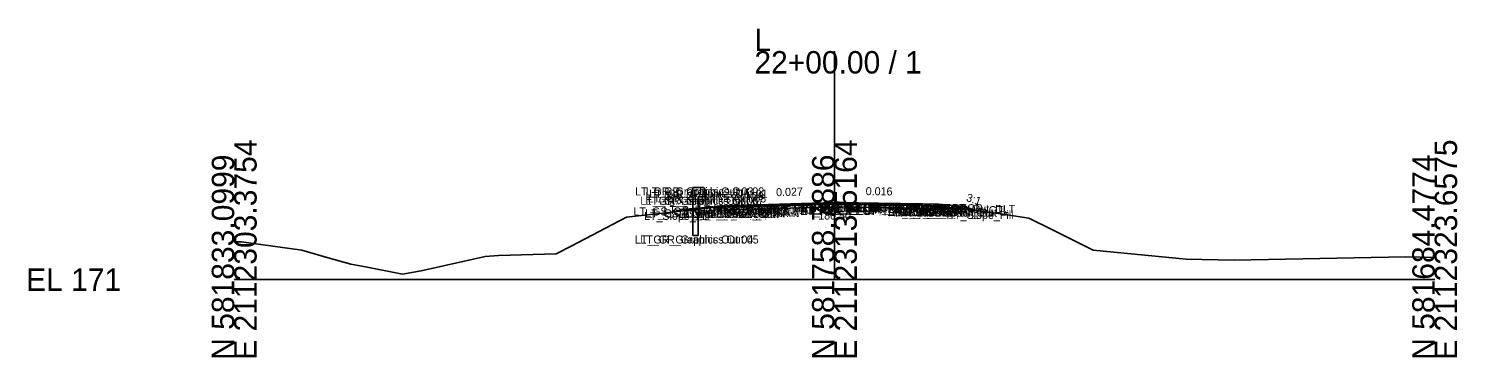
# Model space of a CAD drawing. Extents: x -486 to 1153, y -333 to 9539.
# Drawn here: x 974.3 to 1152.8, y 2990.3 to 3031.3 of the extents above; entities that cross this region are included whole.
import ezdxf

# ---------------------------------------------------------------- set-up
doc = ezdxf.new("R2010")
doc.units = 0
for name, color, linetype in [('Default', 7, 'Continuous'), ('Exist CMT Pavement', 7, 'Continuous'), ('Exist Cross Section Cell', 7, 'Continuous'), ('Exist XS Ground Line', 7, 'Continuous'), ('Prop CMT Guardrail Graphics', 7, 'Continuous'), ('Prop CMT Pvmt Course 1', 7, 'Continuous'), ('Prop CMT Pvmt Course 1 Wedge', 7, 'Continuous'), ('Prop CMT Pvmt Course 2', 7, 'Continuous'), ('Prop CMT Pvmt Course 2 Wedge', 7, 'Continuous'), ('Prop CMT Pvmt Course 3', 7, 'Continuous'), ('Prop CMT Pvmt Course 3 Wedge', 7, 'Continuous'), ('Prop CMT Pvmt Surface', 7, 'Continuous'), ('Prop CMT Pvmt Surface Shoulder', 7, 'Continuous'), ('Prop CMT Pvmt Wedge Surface 1', 7, 'Continuous'), ('Prop CMT Pvmt Wedge Surface 2', 7, 'Continuous'), ('Prop CMT Pvmt Wedge Surface 3', 7, 'Continuous'), ('Prop CMT Shld Paved Course 1', 7, 'Continuous'), ('Prop CMT Shld Paved Course 2', 7, 'Continuous'), ('Prop CMT Shld Paved Course 3', 7, 'Continuous'), ('Prop CMT Slope Grass', 7, 'Continuous'), ('Prop CMT Subgrade Earthwork', 7, 'Continuous'), ('Prop XS Earthwork Shape', 7, 'Continuous'), ('Prop XS SE Text', 7, 'Continuous'), ('Prop XS Side Slope Text', 7, 'Continuous'), ('Scratch_Level_0', 7, 'Continuous'), ('Scratch_Level_1', 7, 'Continuous')]:
    doc.layers.add(name, color=color, linetype=linetype)

msp = doc.modelspace()

# ---------------------------------------------------------------- linework, layer by layer
at = {"layer": 'Exist CMT Pavement'}
for points in [[(1065.45, 3009.24), (1075, 3009.5)], [(1075, 3009.5), (1084.6, 3009.35)]]:
    msp.add_lwpolyline(points, dxfattribs=at)
at = {"layer": 'Exist Cross Section Cell'}
for p, q in [((1075, 3000), (1075, 3028.51)), ((1000, 3000), (1075, 3000)), ((1075, 3000), (1150, 3000))]:
    msp.add_line(p, q, dxfattribs=at)
at = {"layer": 'Exist XS Ground Line'}
for p, q in [((1049.03, 3007.8), (1054.27, 3008.38)), ((1054.27, 3008.38), (1059.55, 3008.97)), ((1059.55, 3008.97), (1065.45, 3009.24)), ((1065.45, 3009.24), (1068.43, 3009.32)), ((1068.43, 3009.32), (1074.94, 3009.5)), ((1074.94, 3009.5), (1077.98, 3009.47)), ((1077.98, 3009.47), (1084.61, 3009.35)), ((1084.61, 3009.35), (1090.42, 3008.86)), ((1090.42, 3008.86), (1094.92, 3008.34)), ((1094.92, 3008.34), (1099.29, 3007.67)), ((1042.12, 3004.19), (1049.03, 3007.8)), ((1099.29, 3007.67), (1102.18, 3006.24)), ((1000, 3004.73), (1000.92, 3004.73)), ((1000.92, 3004.73), (1008.46, 3003.69)), ((1102.18, 3006.24), (1107.34, 3003.66)), ((1008.46, 3003.69), (1011.46, 3002.82)), ((1031.34, 3002.89), (1033.01, 3003)), ((1033.01, 3003), (1040.22, 3003.22)), ((1040.22, 3003.22), (1042.12, 3004.19)), ((1107.34, 3003.66), (1118.95, 3002.56)), ((1011.46, 3002.82), (1014.58, 3001.95)), ((1014.58, 3001.95), (1016.39, 3001.58)), ((1016.39, 3001.58), (1021.02, 3000.69)), ((1023.38, 3001.1), (1031.34, 3002.89)), ((1118.95, 3002.56), (1124.96, 3002.44)), ((1124.96, 3002.44), (1146.35, 3002.85)), ((1146.35, 3002.85), (1150, 3002.76)), ((1021.02, 3000.69), (1023.38, 3001.1))]:
    msp.add_line(p, q, dxfattribs=at)
at = {"layer": 'Prop CMT Guardrail Graphics'}
for points in [[(1057.3, 3005.51), (1057.3, 3011.51)], [(1057.3, 3011.51), (1058.63, 3011.51), (1058.9, 3011.22)], [(1058.9, 3010.63), (1058.63, 3010.34), (1057.96, 3010.34)], [(1057.96, 3010.34), (1057.96, 3005.51)], [(1058.9, 3011.22), (1058.63, 3010.93)], [(1058.63, 3010.93), (1058.9, 3010.63)], [(1057.96, 3005.51), (1057.3, 3005.51)]]:
    msp.add_lwpolyline(points, dxfattribs=at)
at = {"layer": 'Prop CMT Pvmt Course 1'}
for points in [[(1075, 3009.61), (1064, 3009.31)], [(1064, 3009.31), (1064, 3009.1)], [(1064, 3009.1), (1065.45, 3009.14)], [(1065.45, 3009.23), (1075, 3009.49)], [(1065.45, 3009.14), (1065.45, 3009.23)], [(1075, 3009.4), (1075, 3009.61)], [(1075, 3009.61), (1086, 3009.44)], [(1075, 3009.4), (1075, 3009.61)], [(1075, 3009.49), (1075, 3009.4), (1075, 3009.4)], [(1084.61, 3009.33), (1075, 3009.49)], [(1075, 3009.49), (1075, 3009.4), (1075, 3009.4)], [(1084.61, 3009.25), (1084.61, 3009.33)], [(1086, 3009.23), (1084.61, 3009.25)], [(1086, 3009.44), (1086, 3009.23)]]:
    msp.add_lwpolyline(points, dxfattribs=at)
at = {"layer": 'Prop CMT Pvmt Course 1 Wedge'}
for points in [[(1075, 3009.49), (1065.45, 3009.23)], [(1075, 3009.49), (1084.61, 3009.33)]]:
    msp.add_lwpolyline(points, dxfattribs=at)
at = {"layer": 'Prop CMT Pvmt Course 2'}
for points in [[(1065.45, 3009.14), (1064, 3009.1)], [(1064, 3009.1), (1064, 3008.77)], [(1064, 3008.77), (1065.45, 3008.81)], [(1065.45, 3008.81), (1065.45, 3009.14)], [(1084.61, 3008.92), (1084.61, 3009.25)], [(1084.61, 3009.25), (1086, 3009.23)], [(1086, 3008.9), (1084.61, 3008.92)], [(1086, 3009.23), (1086, 3008.9)]]:
    msp.add_lwpolyline(points, dxfattribs=at)
at = {"layer": 'Prop CMT Pvmt Course 2 Wedge'}
for points in [[(1075, 3009.4), (1065.45, 3009.14)], [(1075, 3009.4), (1084.61, 3009.25)]]:
    msp.add_lwpolyline(points, dxfattribs=at)
at = {"layer": 'Prop CMT Pvmt Course 3'}
for points in [[(1065.45, 3008.81), (1064, 3008.77)], [(1064, 3008.77), (1064, 3008.77)], [(1065.45, 3008.81), (1065.45, 3008.81)], [(1084.61, 3008.92), (1086, 3008.9)], [(1084.61, 3008.92), (1084.61, 3008.92)], [(1086, 3008.9), (1086, 3008.9)]]:
    msp.add_lwpolyline(points, dxfattribs=at)
at = {"layer": 'Prop CMT Pvmt Course 3 Wedge'}
for points in [[(1075, 3009.07), (1065.45, 3008.81)], [(1075, 3009.07), (1084.61, 3008.92)]]:
    msp.add_lwpolyline(points, dxfattribs=at)
at = {"layer": 'Prop CMT Pvmt Surface'}
for points in [[(1075, 3009.61), (1064, 3009.31)], [(1075, 3009.61), (1086, 3009.44)]]:
    msp.add_lwpolyline(points, dxfattribs=at)
at = {"layer": 'Prop CMT Pvmt Surface Shoulder'}
for points in [[(1064, 3009.31), (1062, 3009.26)], [(1086, 3009.44), (1088, 3009.41)]]:
    msp.add_lwpolyline(points, dxfattribs=at)
at = {"layer": 'Prop CMT Pvmt Wedge Surface 1'}
for points in [[(1064, 3009.1), (1064, 3009.31)], [(1065.45, 3009.14), (1064, 3009.1)], [(1075, 3009.49), (1065.45, 3009.23)], [(1065.45, 3009.23), (1065.45, 3009.14)], [(1075, 3009.49), (1084.61, 3009.33)], [(1084.61, 3009.33), (1084.61, 3009.25)], [(1084.61, 3009.25), (1086, 3009.23)], [(1086, 3009.23), (1086, 3009.44)]]:
    msp.add_lwpolyline(points, dxfattribs=at)
at = {"layer": 'Prop CMT Pvmt Wedge Surface 2'}
for points in [[(1075, 3009.4), (1064, 3009.1)], [(1064, 3009.1), (1064, 3009.31)], [(1075, 3009.4), (1086, 3009.23)], [(1086, 3009.23), (1086, 3009.44)]]:
    msp.add_lwpolyline(points, dxfattribs=at)
at = {"layer": 'Prop CMT Pvmt Wedge Surface 3'}
for points in [[(1064, 3008.77), (1064, 3009.31)], [(1075, 3009.07), (1064, 3008.77)], [(1075, 3009.07), (1086, 3008.9)], [(1086, 3008.9), (1086, 3009.44)]]:
    msp.add_lwpolyline(points, dxfattribs=at)
at = {"layer": 'Prop CMT Shld Paved Course 1'}
for points in [[(1064, 3009.31), (1062, 3009.26), (1061.79, 3009.04)], [(1061.79, 3009.04), (1064, 3009.1)], [(1064, 3009.1), (1064, 3009.31)], [(1086, 3009.44), (1088, 3009.41), (1088.21, 3009.19)], [(1086, 3009.23), (1086, 3009.44)], [(1088.21, 3009.19), (1086, 3009.23)]]:
    msp.add_lwpolyline(points, dxfattribs=at)
at = {"layer": 'Prop CMT Shld Paved Course 2'}
for points in [[(1064, 3009.1), (1061.79, 3009.04), (1061.44, 3008.7)], [(1061.44, 3008.7), (1064, 3008.77)], [(1064, 3008.77), (1064, 3009.1)], [(1086, 3009.23), (1088.21, 3009.19), (1088.55, 3008.86)], [(1086, 3008.9), (1086, 3009.23)], [(1088.55, 3008.86), (1086, 3008.9)]]:
    msp.add_lwpolyline(points, dxfattribs=at)
at = {"layer": 'Prop CMT Shld Paved Course 3'}
for points in [[(1064, 3008.77), (1061.44, 3008.7)], [(1061.44, 3008.7), (1061.44, 3008.7), (1061.44, 3008.7)], [(1064, 3008.77), (1064, 3008.77)], [(1086, 3008.9), (1088.55, 3008.86)], [(1086, 3008.9), (1086, 3008.9)], [(1088.55, 3008.86), (1088.55, 3008.86), (1088.55, 3008.86)]]:
    msp.add_lwpolyline(points, dxfattribs=at)
at = {"layer": 'Prop CMT Slope Grass'}
for points in [[(1055.9, 3008.77), (1054.96, 3008.46)], [(1058.9, 3009.01), (1055.9, 3008.77)], [(1062, 3009.26), (1058.9, 3009.01)], [(1088, 3009.41), (1091, 3009.18), (1092.8, 3008.58)]]:
    msp.add_lwpolyline(points, dxfattribs=at)
at = {"layer": 'Prop CMT Subgrade Earthwork'}
for points in [[(1061.44, 3008.7), (1060.97, 3009.17)], [(1064, 3008.77), (1061.44, 3008.7)], [(1065.45, 3008.81), (1064, 3008.77)], [(1065.45, 3008.81), (1065.45, 3009.24)], [(1084.61, 3008.92), (1084.6, 3009.35)], [(1084.61, 3008.92), (1086, 3008.9)], [(1086, 3008.9), (1088.55, 3008.86)], [(1088.55, 3008.86), (1089.02, 3009.33)]]:
    msp.add_lwpolyline(points, dxfattribs=at)
at = {"layer": 'Prop XS Earthwork Shape'}
for points in [[(1061.1, 3009.04), (1060.97, 3009.17), (1058.9, 3009.01), (1055.9, 3008.77), (1054.96, 3008.46), (1059.55, 3008.97)], [(1064, 3008.77), (1061.44, 3008.7), (1061.1, 3009.04), (1065.45, 3009.24), (1065.45, 3008.81)], [(1068.43, 3009.32), (1072.78, 3009.44), (1065.45, 3009.24)], [(1072.78, 3009.44), (1074.94, 3009.5), (1075, 3009.5)], [(1075, 3009.5), (1077.98, 3009.47), (1084.6, 3009.35)], [(1084.6, 3009.35), (1088.7, 3009), (1088.55, 3008.86), (1086, 3008.9), (1084.61, 3008.92)], [(1089.02, 3009.33), (1091, 3009.18), (1092.8, 3008.58), (1090.42, 3008.86), (1088.7, 3009)]]:
    msp.add_lwpolyline(points, close=True, dxfattribs=at)
at = {"layer": 'Scratch_Level_1'}
for p, q in [((1065.45, 3009.24), (1068.43, 3009.32)), ((1068.43, 3009.32), (1074.94, 3009.5)), ((1074.94, 3009.61), (1077.99, 3009.57)), ((1074.94, 3009.5), (1075.83, 3009.49))]:
    msp.add_line(p, q, dxfattribs=at)
for points in [[(1075, 3009.51), (1065.45, 3009.25)], [(1065.45, 3009.25), (1065.45, 3009.24)], [(1075, 3009.51), (1086, 3009.33)], [(1075.83, 3009.49), (1075, 3009.51)]]:
    msp.add_lwpolyline(points, dxfattribs=at)

# ---------------------------------------------------------------- texts
at = {"layer": 'Default'}
for s, height, p in [('180.50', 1, (1072.97, 3007.5)), ('-', 0.0001, (1000, 3000))]:
    msp.add_text(s, height=height, dxfattribs=at).set_placement(p)
at = {"layer": 'Exist Cross Section Cell'}
for s, p in [('L', (1065, 3028.51)), ('22+00.00 / 1', (1065, 3025.71)), ('EL 171', (974, 2998.6))]:
    msp.add_text(s, height=2.8, dxfattribs=at).set_placement(p)
for s, p in [('E 2112303.3754', (1002.8, 2990)), ('E 2112313.5164', (1077.8, 2990)), ('E 2112323.6575', (1152.8, 2990)), ('N 581833.0999', (1000, 2990)), ('N 581758.7886', (1075, 2990)), ('N 581684.4774', (1150, 2990))]:
    msp.add_text(s, height=2.8, rotation=90, dxfattribs=at).set_placement(p)
at = {"layer": 'Prop XS SE Text'}
for s, rotation, p in [('0.027', 1.5581, (1067.72, 3010.41)), ('0.016', 359.1005, (1078.9, 3010.55))]:
    msp.add_text(s, height=1, rotation=rotation, dxfattribs=at).set_placement(p)
at = {"layer": 'Prop XS Side Slope Text'}
for rotation, p in [(18.2629, (1054.44, 3009.08)), (341.7371, (1091.38, 3009.84))]:
    msp.add_text('3:1', height=1, rotation=rotation, dxfattribs=at).set_placement(p)
at = {"layer": 'Scratch_Level_0'}
for s, p in [('LT_GR_Graphics Out 03', (1050.08, 3010.51)), ('LT_GR_Graphics Out 06', (1050.74, 3009.34)), ('LT_GR_Graphics Out 07', (1051.39, 3009.34)), ('LT_GR_Graphics Out 09', (1051.4, 3009.93)), ('LT_GR_Graphics Out 02', (1051.43, 3010.51)), ('LT_GR_Graphics Out 08', (1051.67, 3009.63)), ('LT_GR_Graphics Out 01', (1051.85, 3010.22)), ('LT_GS_OS_GR_Face_Graphics', (1049.9, 3008.01)), ('LT_Slope_Fill', (1051.2, 3007.46)), ('LT_GS_OS_CTL', (1051.36, 3007.77)), ('LT_Sub_Trench_Out_DLT', (1053.62, 3008.17)), ('LT_Sub_Trench_Out', (1055.55, 3007.7)), ('LT_PS3_Shelf_Out', (1056.1, 3007.7)), ('LT_PS3_OEOP', (1057.23, 3007.7)), ('LT_PS2_OEOP', (1057.57, 3008.04)), ('LT_PS1_OEOP', (1057.91, 3008.26)), ('LT_PV2_OEOT', (1059.75, 3008.1)), ('LT_PV3_OEOT', (1059.75, 3007.77)), ('LT_Sub_OEOT', (1059.77, 3007.77)), ('LT_PV1_OEOT', (1059.87, 3008.31)), ('LT_PV_OEEOP_EG', (1060.05, 3008.24)), ('LT_Sub Tie Out', (1060.61, 3008.24)), ('LT_PV2_OEEOP', (1060.84, 3008.14)), ('LT_PV3_OEEOP', (1060.84, 3007.81)), ('LT_Sub_OEEOP', (1060.87, 3007.81)), ('LT_PV1_OEEOP', (1060.96, 3008.23)), ('RT_PV_IEEOP_EG', (1069.92, 3008.5)), ('LT_PV_IEEOP_EG', (1069.98, 3008.5)), ('RT_PV2_IEEOP', (1070.71, 3008.4)), ('RT_PV3_IEEOP', (1070.71, 3008.07)), ('LT_PV2_IEEOP', (1070.77, 3008.4)), ('LT_PV3_IEEOP', (1070.77, 3008.07)), ('RT_PV1_IEEOP', (1070.83, 3008.49)), ('LT_PV1_IEEOP', (1070.89, 3008.49)), ('PV2_PGL', (1072.35, 3008.4)), ('PV1_PGL', (1072.47, 3008.61)), ('RT_PV_OEEOP_EG', (1079.14, 3008.35)), ('RT_Sub Tie Out', (1079.7, 3008.35)), ('RT_PV2_OEEOP', (1079.94, 3008.25)), ('RT_PV3_OEEOP', (1079.94, 3007.92)), ('RT_Sub_OEEOP', (1079.96, 3007.92)), ('RT_PV1_OEEOP', (1080.06, 3008.33)), ('RT_Sub_Trench_Out_DLT', (1081.61, 3008.33)), ('RT_PV2_OEOT', (1081.69, 3008.23)), ('RT_PV3_OEOT', (1081.69, 3007.9)), ('RT_Sub_OEOT', (1081.71, 3007.9)), ('RT_PV1_OEOT', (1081.81, 3008.44)), ('RT_Sub_Trench_Out', (1082.6, 3007.86)), ('RT_PS3_Shelf_Out', (1083.15, 3007.86)), ('RT_PS1_OEOP', (1083.85, 3008.41)), ('RT_PS2_OEOP', (1083.94, 3008.19)), ('RT_PS3_OEOP', (1084.28, 3007.86)), ('RT_GS_OS_CTL', (1086.4, 3008.18)), ('RT_Slope_Fill', (1088.98, 3007.58)), ('LT_GR_Graphics Out 04', (1050.07, 3004.51)), ('LT_GR_Graphics Out 05', (1050.74, 3004.51))]:
    msp.add_text(s, height=1, dxfattribs=at).set_placement(p)

doc.saveas('drawing.dxf')
